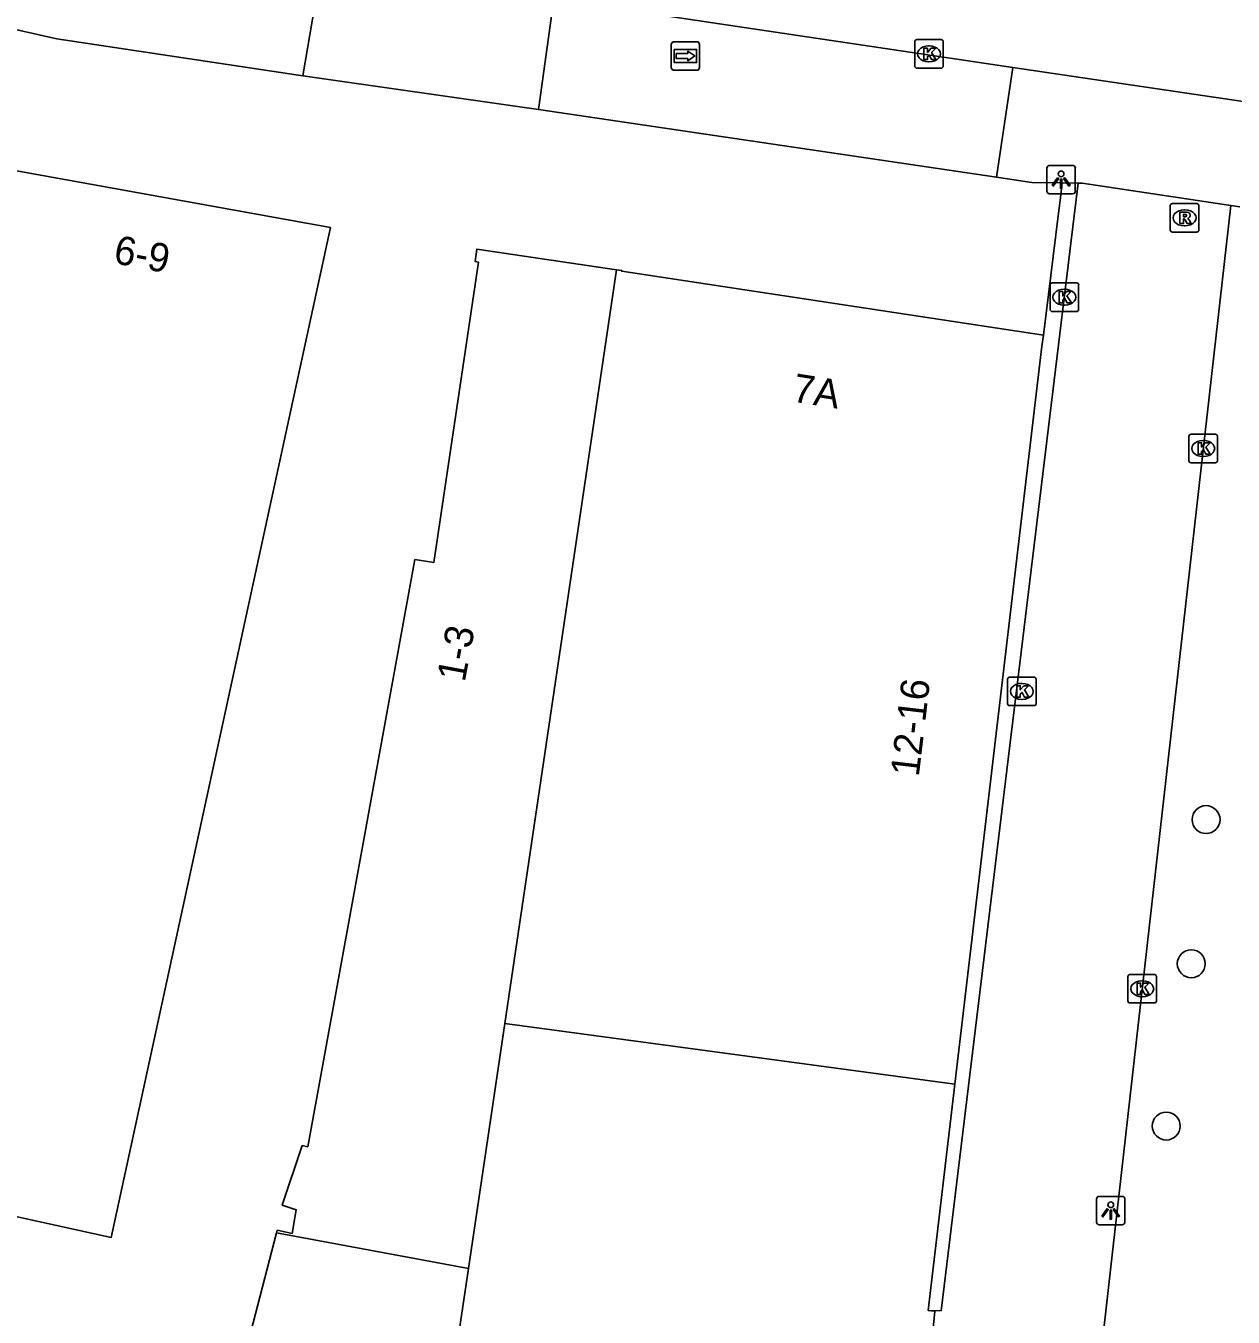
# Model space of a CAD drawing. Extents: x 163010 to 163853, y 382793 to 383982.
# Drawn here: x 163286.47 to 163328.77, y 382961.39 to 383006.66 of the extents above; entities that cross this region are included whole.
import ezdxf

# ---------------------------------------------------------------- set-up
doc = ezdxf.new("R2010")
doc.units = 0
for name, color, linetype in [('IMGEO_Boom', 7, 'Continuous'), ('IMGEO_Kolk', 7, 'Continuous'), ('IMGEO_Lichtpunt', 7, 'Continuous'), ('IMGEO_Pand', 7, 'Continuous'), ('IMGEO_Pand_nummerreeks', 7, 'Continuous'), ('IMGEO_Rijbaan_lokaal_gesloten', 7, 'Continuous'), ('IMGEO_Rijbaan_lokaal_open', 7, 'Continuous'), ('IMGEO_Rioolput', 7, 'Continuous'), ('IMGEO_Voetpad_open', 7, 'Continuous'), ('IMGEO_Wegwijzer', 7, 'Continuous')]:
    doc.layers.add(name, color=color, linetype=linetype)

msp = doc.modelspace()

# ---------------------------------------------------------------- linework, layer by layer
at = {"layer": 'IMGEO_Boom'}
for centre in [(163327.818, 382978.836), (163327.299, 382973.781), (163326.422, 382968.093)]:
    msp.add_circle(centre, 0.489, dxfattribs=at)
at = {"layer": 'IMGEO_Kolk'}
for p, q in [((163317.609, 383005.249), (163317.609, 383006.101)), ((163317.684, 383006.175), (163318.536, 383006.175)), ((163318.097, 383005.955), (163318.122, 383005.955)), ((163318.61, 383006.101), (163318.61, 383005.249)), ((163318.536, 383005.175), (163317.684, 383005.175)), ((163318.12, 383005.395), (163318.095, 383005.395)), ((163322.353, 382996.72), (163322.353, 382997.572)), ((163322.428, 382997.646), (163323.28, 382997.646)), ((163322.841, 382997.426), (163322.866, 382997.426)), ((163323.354, 382997.572), (163323.354, 382996.72)), ((163322.864, 382996.866), (163322.839, 382996.866)), ((163323.28, 382996.646), (163322.428, 382996.646)), ((163327.293, 382992.343), (163328.145, 382992.343)), ((163327.218, 382991.417), (163327.218, 382992.269)), ((163327.706, 382992.123), (163327.731, 382992.123)), ((163328.219, 382992.269), (163328.219, 382991.417)), ((163327.729, 382991.563), (163327.704, 382991.563)), ((163328.145, 382991.343), (163327.293, 382991.343)), ((163320.862, 382982.904), (163320.862, 382983.756)), ((163320.937, 382983.83), (163321.789, 382983.83)), ((163321.863, 382983.756), (163321.863, 382982.904)), ((163321.35, 382983.61), (163321.375, 382983.61)), ((163321.789, 382982.83), (163320.937, 382982.83)), ((163321.373, 382983.05), (163321.348, 382983.05)), ((163325.08, 382972.481), (163325.08, 382973.333)), ((163325.155, 382973.407), (163326.007, 382973.407)), ((163326.081, 382973.333), (163326.081, 382972.481)), ((163325.568, 382973.187), (163325.593, 382973.187)), ((163326.007, 382972.407), (163325.155, 382972.407)), ((163325.591, 382972.627), (163325.566, 382972.627))]:
    msp.add_line(p, q, dxfattribs=at)
for points in [[(163317.609, 383005.249), (163317.609, 383006.101)], [(163317.684, 383006.175), (163318.536, 383006.175)], [(163317.93, 383005.875), (163318.053, 383005.875), (163318.053, 383005.724), (163318.183, 383005.875), (163318.347, 383005.875), (163318.201, 383005.724), (163318.354, 383005.475), (163318.202, 383005.475), (163318.117, 383005.639), (163318.053, 383005.572), (163318.053, 383005.475), (163317.93, 383005.475), (163317.93, 383005.875)], [(163318.61, 383006.101), (163318.61, 383005.249)], [(163318.536, 383005.175), (163317.684, 383005.175)], [(163322.353, 382996.72), (163322.353, 382997.572)], [(163322.428, 382997.646), (163323.28, 382997.646)], [(163322.674, 382997.346), (163322.797, 382997.346), (163322.797, 382997.195), (163322.927, 382997.346), (163323.091, 382997.346), (163322.945, 382997.195), (163323.098, 382996.946), (163322.946, 382996.946), (163322.861, 382997.11), (163322.797, 382997.043), (163322.797, 382996.946), (163322.674, 382996.946), (163322.674, 382997.346)], [(163323.354, 382997.572), (163323.354, 382996.72)], [(163323.28, 382996.646), (163322.428, 382996.646)], [(163327.293, 382992.343), (163328.145, 382992.343)], [(163327.218, 382991.417), (163327.218, 382992.269)], [(163327.539, 382992.043), (163327.662, 382992.043), (163327.662, 382991.892), (163327.792, 382992.043), (163327.956, 382992.043), (163327.81, 382991.892), (163327.963, 382991.643), (163327.811, 382991.643), (163327.726, 382991.807), (163327.662, 382991.74), (163327.662, 382991.643), (163327.539, 382991.643), (163327.539, 382992.043)], [(163328.219, 382992.269), (163328.219, 382991.417)], [(163328.145, 382991.343), (163327.293, 382991.343)], [(163320.862, 382982.904), (163320.862, 382983.756)], [(163320.937, 382983.83), (163321.789, 382983.83)], [(163321.863, 382983.756), (163321.863, 382982.904)], [(163321.183, 382983.53), (163321.306, 382983.53), (163321.306, 382983.379), (163321.436, 382983.53), (163321.6, 382983.53), (163321.454, 382983.379), (163321.607, 382983.13), (163321.455, 382983.13), (163321.37, 382983.294), (163321.306, 382983.227), (163321.306, 382983.13), (163321.183, 382983.13), (163321.183, 382983.53)], [(163321.789, 382982.83), (163320.937, 382982.83)], [(163325.08, 382972.481), (163325.08, 382973.333)], [(163325.155, 382973.407), (163326.007, 382973.407)], [(163326.081, 382973.333), (163326.081, 382972.481)], [(163325.401, 382973.107), (163325.524, 382973.107), (163325.524, 382972.956), (163325.654, 382973.107), (163325.818, 382973.107), (163325.672, 382972.956), (163325.825, 382972.707), (163325.673, 382972.707), (163325.588, 382972.871), (163325.524, 382972.804), (163325.524, 382972.707), (163325.401, 382972.707), (163325.401, 382973.107)], [(163326.007, 382972.407), (163325.155, 382972.407)]]:
    msp.add_lwpolyline(points, dxfattribs=at)
for centre, start, end in [((163317.686, 383006.099), 91.552, 178.448), ((163317.686, 383006.099), 91.552, 178.448), ((163318.534, 383006.099), 1.552, 88.448), ((163318.534, 383006.099), 1.552, 88.448), ((163317.686, 383005.251), 181.552, 268.448), ((163317.686, 383005.251), 181.552, 268.448), ((163318.534, 383005.251), 271.552, 358.448), ((163318.534, 383005.251), 271.552, 358.448), ((163322.43, 382997.57), 91.552, 178.448), ((163322.43, 382997.57), 91.552, 178.448), ((163323.278, 382997.57), 1.552, 88.448), ((163323.278, 382997.57), 1.552, 88.448), ((163322.43, 382996.722), 181.552, 268.448), ((163322.43, 382996.722), 181.552, 268.448), ((163323.278, 382996.722), 271.552, 358.448), ((163323.278, 382996.722), 271.552, 358.448), ((163327.295, 382992.267), 91.552, 178.448), ((163327.295, 382992.267), 91.552, 178.448), ((163328.143, 382992.267), 1.552, 88.448), ((163328.143, 382992.267), 1.552, 88.448), ((163327.295, 382991.419), 181.552, 268.448), ((163327.295, 382991.419), 181.552, 268.448), ((163328.143, 382991.419), 271.552, 358.448), ((163328.143, 382991.419), 271.552, 358.448), ((163320.939, 382983.754), 91.552, 178.448), ((163320.939, 382983.754), 91.552, 178.448), ((163321.787, 382983.754), 1.552, 88.448), ((163321.787, 382983.754), 1.552, 88.448), ((163320.939, 382982.906), 181.552, 268.448), ((163320.939, 382982.906), 181.552, 268.448), ((163321.787, 382982.906), 271.552, 358.448), ((163321.787, 382982.906), 271.552, 358.448), ((163325.157, 382973.331), 91.552, 178.448), ((163325.157, 382973.331), 91.552, 178.448), ((163326.005, 382973.331), 1.552, 88.448), ((163326.005, 382973.331), 1.552, 88.448), ((163325.157, 382972.483), 181.552, 268.448), ((163325.157, 382972.483), 181.552, 268.448), ((163326.005, 382972.483), 271.552, 358.448), ((163326.005, 382972.483), 271.552, 358.448)]:
    msp.add_arc(centre, 0.0765, start, end, dxfattribs=at)
for centre, major_axis, ratio, start_param, end_param in [((163318.096, 383005.675), (-0.387, 0.002), 0.722429, 4.712389, 7.853982), ((163318.121, 383005.675), (-0.39, 0.002), 0.717154, 1.570796, 4.712389), ((163322.84, 382997.146), (-0.387, 0.002), 0.722429, 4.712389, 7.853982), ((163322.865, 382997.146), (-0.39, 0.002), 0.717154, 1.570796, 4.712389), ((163327.705, 382991.843), (-0.387, 0.002), 0.722429, 4.712389, 7.853982), ((163327.73, 382991.843), (-0.39, 0.002), 0.717154, 1.570796, 4.712389), ((163321.349, 382983.33), (-0.387, 0.002), 0.722429, 4.712389, 7.853982), ((163321.374, 382983.33), (-0.39, 0.002), 0.717154, 1.570796, 4.712389), ((163325.567, 382972.907), (-0.387, 0.002), 0.722429, 4.712389, 7.853982), ((163325.592, 382972.907), (-0.39, 0.002), 0.717154, 1.570796, 4.712389)]:
    msp.add_ellipse(centre, major_axis=major_axis, ratio=ratio, start_param=start_param, end_param=end_param, dxfattribs=at)
at = {"layer": 'IMGEO_Lichtpunt'}
for p, q in [((163322.241, 383001.671), (163322.241, 383000.864)), ((163322.241, 383001.671), (163322.241, 383000.864)), ((163323.143, 383001.766), (163322.335, 383001.766)), ((163323.143, 383001.766), (163322.335, 383001.766)), ((163323.237, 383000.864), (163323.237, 383001.671)), ((163323.237, 383000.864), (163323.237, 383001.671)), ((163322.335, 383000.77), (163323.143, 383000.77)), ((163322.335, 383000.77), (163323.143, 383000.77)), ((163324.881, 382965.629), (163324.073, 382965.629)), ((163324.881, 382965.629), (163324.073, 382965.629)), ((163323.979, 382965.534), (163323.979, 382964.727)), ((163323.979, 382965.534), (163323.979, 382964.727)), ((163324.975, 382964.727), (163324.975, 382965.534)), ((163324.975, 382964.727), (163324.975, 382965.534)), ((163324.073, 382964.633), (163324.881, 382964.633)), ((163324.073, 382964.633), (163324.881, 382964.633))]:
    msp.add_line(p, q, dxfattribs=at)
for points in [[(163322.615, 383001.335), (163322.654, 383001.307), (163322.466, 383001.045), (163322.428, 383001.072), (163322.615, 383001.335)], [(163322.717, 383001.287), (163322.764, 383001.287), (163322.764, 383000.965), (163322.717, 383000.965), (163322.717, 383001.287)], [(163322.827, 383001.307), (163322.865, 383001.334), (163323.052, 383001.072), (163323.013, 383001.044), (163322.827, 383001.307)], [(163324.353, 382965.198), (163324.392, 382965.17), (163324.204, 382964.908), (163324.166, 382964.935), (163324.353, 382965.198)], [(163324.455, 382965.15), (163324.502, 382965.15), (163324.502, 382964.828), (163324.455, 382964.828), (163324.455, 382965.15)], [(163324.565, 382965.17), (163324.603, 382965.197), (163324.79, 382964.935), (163324.751, 382964.907), (163324.565, 382965.17)]]:
    msp.add_lwpolyline(points, dxfattribs=at)
for centre in [(163322.74, 383001.469), (163324.478, 382965.332)]:
    msp.add_circle(centre, 0.0994, dxfattribs=at)
for centre, start, end in [((163322.335, 383001.671), 90, 180), ((163322.335, 383001.671), 90, 180), ((163323.143, 383001.671), 0, 90), ((163323.143, 383001.671), 0, 90), ((163322.335, 383000.864), 180, 270), ((163322.335, 383000.864), 180, 270), ((163323.143, 383000.864), 270, 0), ((163323.143, 383000.864), 270, 360), ((163324.073, 382965.534), 90, 180), ((163324.073, 382965.534), 90, 180), ((163324.881, 382965.534), 0, 90), ((163324.881, 382965.534), 0, 90), ((163324.073, 382964.727), 180, 270), ((163324.073, 382964.727), 180, 270), ((163324.881, 382964.727), 270, 0), ((163324.881, 382964.727), 270, 360)]:
    msp.add_arc(centre, 0.0946, start, end, dxfattribs=at)
at = {"layer": 'IMGEO_Pand'}
for points in [[(163269.797, 382931.333), (163283.432, 382928.405), (163283.861, 382930.425), (163282.754, 382934.58), (163278.384, 382935.538), (163284.933, 382965.176), (163289.462, 382964.19), (163297.137, 382999.587), (163285.357, 383001.72)], [(163307.166, 382998.108), (163302.273, 382998.834), (163302.204, 382998.4), (163302.321, 382998.381), (163300.76, 382987.844), (163300.097, 382987.952), (163296.342, 382967.366), (163296.149, 382967.407), (163295.452, 382965.32), (163295.942, 382965.157), (163295.792, 382964.33), (163295.278, 382964.44), (163295.254, 382964.347)], [(163307.166, 382998.108), (163303.249, 382971.693)], [(163322.117, 382995.812), (163307.343, 382998.058), (163307.347, 382998.081), (163307.166, 382998.108)], [(163319.02, 382969.566), (163322.069, 382995.428), (163322.117, 382995.812)], [(163301.974, 382963.099), (163303.249, 382971.693)], [(163303.249, 382971.693), (163319.02, 382969.566)], [(163319.02, 382969.566), (163318.085, 382961.631)], [(163295.254, 382964.347), (163287.208, 382933.335), (163288.44, 382929.261), (163296.67, 382927.914), (163297.162, 382931.151)], [(163301.974, 382963.099), (163295.254, 382964.347)], [(163301.138, 382957.46), (163301.974, 382963.099)], [(163317.528, 382954.837), (163317.842, 382956.828), (163318.317, 382961.605), (163318.085, 382961.631)]]:
    msp.add_lwpolyline(points, dxfattribs=at)
at = {"layer": 'IMGEO_Rijbaan_lokaal_gesloten'}
for points in [[(163304.96, 383007.61), (163321.045, 383005.203)], [(163321.045, 383005.203), (163329.509, 383003.951)], [(163318.085, 382961.631), (163318.535, 382961.62), (163323.199, 383000), (163323.335, 383001.142)], [(163328.682, 383000.362), (163323.479, 383001.139), (163323.335, 383001.142)], [(163328.682, 383000.362), (163320.711, 382929.78), (163328.183, 382928.813), (163326.434, 382916.263), (163324.274, 382916.519)]]:
    msp.add_lwpolyline(points, dxfattribs=at)
at = {"layer": 'IMGEO_Rijbaan_lokaal_open'}
for points in [[(163322.779, 383001.151), (163322.703, 383000.538), (163322.636, 383000), (163322.117, 382995.812)], [(163323.335, 383001.142), (163322.779, 383001.151)]]:
    msp.add_lwpolyline(points, dxfattribs=at)
at = {"layer": 'IMGEO_Rioolput'}
for p, q in [((163326.565, 382999.504), (163326.565, 383000.356)), ((163326.64, 383000.43), (163327.492, 383000.43)), ((163327.053, 383000.21), (163327.078, 383000.21)), ((163327.566, 383000.356), (163327.566, 382999.504)), ((163327.076, 382999.65), (163327.051, 382999.65)), ((163327.492, 382999.43), (163326.64, 382999.43))]:
    msp.add_line(p, q, dxfattribs=at)
for points in [[(163326.565, 382999.504), (163326.565, 383000.356)], [(163326.64, 383000.43), (163327.492, 383000.43)], [(163327.154, 383000.128), (163326.902, 383000.13), (163326.902, 382999.73)], [(163327.08, 383000.049), (163327.026, 383000.049), (163327.026, 382999.968)], [(163327.566, 383000.356), (163327.566, 382999.504)], [(163326.902, 382999.73), (163327.026, 382999.73), (163327.026, 382999.892), (163327.037, 382999.892)], [(163327.026, 382999.968), (163327.078, 382999.968)], [(163327.084, 382999.863), (163327.155, 382999.73), (163327.295, 382999.73), (163327.23, 382999.856)], [(163327.492, 382999.43), (163326.64, 382999.43)]]:
    msp.add_lwpolyline(points, dxfattribs=at)
for centre, radius, start, end in [((163326.642, 383000.354), 0.0765, 91.552, 178.448), ((163326.642, 383000.354), 0.0765, 91.552, 178.448), ((163327.086, 382999.953), 0.0964, 77.0061, 93.1865), ((163327.1, 383000.01), 0.0378, 276.6634, 79.6772), ((163327.153, 383000.018), 0.109, 350.3612, 89.416), ((163327.151, 383000.018), 0.112, 277.5842, 350.9817), ((163327.49, 383000.354), 0.0765, 1.552, 88.448), ((163327.49, 383000.354), 0.0765, 1.552, 88.448), ((163327.036, 382999.839), 0.0533, 26.0293, 88.6989), ((163327.062, 383000.157), 0.19, 274.7715, 282.9687), ((163327.135, 382999.803), 0.108, 29.5134, 73.7905), ((163326.642, 382999.506), 0.0765, 181.552, 268.448), ((163326.642, 382999.506), 0.0765, 181.552, 268.448), ((163327.49, 382999.506), 0.0765, 271.552, 358.448), ((163327.49, 382999.506), 0.0765, 271.552, 358.448)]:
    msp.add_arc(centre, radius, start, end, dxfattribs=at)
for centre, major_axis, ratio, start_param, end_param in [((163327.052, 382999.93), (-0.387, 0.002), 0.722429, 4.712389, 7.853982), ((163327.077, 382999.93), (-0.39, 0.002), 0.717154, 1.570796, 4.712389)]:
    msp.add_ellipse(centre, major_axis=major_axis, ratio=ratio, start_param=start_param, end_param=end_param, dxfattribs=at)
at = {"layer": 'IMGEO_Voetpad_open'}
for points in [[(163273.131, 383009.46), (163287.555, 383006.208), (163296.167, 383004.907)], [(163296.167, 383004.907), (163296.84, 383008.817)], [(163304.431, 383003.722), (163304.96, 383007.61)], [(163321.045, 383005.203), (163320.479, 383001.357)], [(163304.431, 383003.722), (163296.167, 383004.907)], [(163320.479, 383001.357), (163304.431, 383003.722)], [(163322.779, 383001.151), (163321.716, 383001.17), (163320.479, 383001.357)], [(163329, 383000.314), (163328.682, 383000.362)]]:
    msp.add_lwpolyline(points, dxfattribs=at)
at = {"layer": 'IMGEO_Wegwijzer'}
for p, q in [((163309.081, 383005.203), (163309.081, 383006.003)), ((163309.081, 383006.003), (163309.081, 383005.203)), ((163309.181, 383006.103), (163309.971, 383006.103)), ((163309.971, 383006.103), (163309.181, 383006.103)), ((163310.071, 383006.003), (163310.071, 383005.203)), ((163310.071, 383005.203), (163310.071, 383006.003)), ((163309.971, 383005.103), (163309.181, 383005.103)), ((163309.181, 383005.103), (163309.971, 383005.103))]:
    msp.add_line(p, q, dxfattribs=at)
for points in [[(163309.182, 383005.835), (163309.97, 383005.835), (163309.97, 383005.371), (163309.182, 383005.371), (163309.182, 383005.835)], [(163309.247, 383005.687), (163309.247, 383005.603), (163309.247, 383005.519), (163309.658, 383005.519), (163309.658, 383005.436), (163309.905, 383005.603), (163309.658, 383005.77), (163309.658, 383005.687), (163309.247, 383005.687)]]:
    msp.add_lwpolyline(points, dxfattribs=at)
for centre, start, end in [((163309.181, 383006.003), 90, 180), ((163309.181, 383006.003), 90, 180), ((163309.971, 383006.003), 0, 90), ((163309.971, 383006.003), 360, 90), ((163309.181, 383005.203), 180, 270), ((163309.181, 383005.203), 180, 270), ((163309.971, 383005.203), 270, 0), ((163309.971, 383005.203), 270, 0)]:
    msp.add_arc(centre, 0.1, start, end, dxfattribs=at)

# ---------------------------------------------------------------- texts
at = {"layer": 'IMGEO_Pand_nummerreeks'}
for s, rotation, p in [('6-9', 349.2742, (163289.502, 382998.348)), ('7A', 351.0389, (163313.289, 382993.492)), ('1-3', 79.4635, (163301.845, 382983.63)), ('12-16', 83.2794, (163317.751, 382980.315))]:
    msp.add_text(s, height=1, rotation=rotation, dxfattribs=at).set_placement(p)

doc.saveas('drawing.dxf')
